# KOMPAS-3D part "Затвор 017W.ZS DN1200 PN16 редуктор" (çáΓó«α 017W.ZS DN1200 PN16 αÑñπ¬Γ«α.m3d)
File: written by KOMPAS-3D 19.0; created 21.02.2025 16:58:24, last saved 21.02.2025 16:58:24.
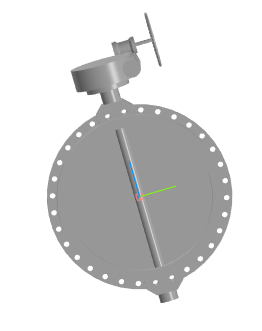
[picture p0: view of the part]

Document properties: Автор: Евгений; Полное имя файла: Затвор 017W.ZS DN1200 PN16 редуктор.a3d

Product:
- Part/product: Затвор 017W.ZS DN1200 PN16 редуктор
    Масса: 1594.93

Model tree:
1. Операция без истории:1  (labels: 0Ā0␣/␣/Ā0␣/Ā0Ȁ0␣/␣/Ȁ0␣/Ȁ0̀0␣/␣/̀0␣/̀0Ѐ0␣/␣/Ѐ0␣/)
